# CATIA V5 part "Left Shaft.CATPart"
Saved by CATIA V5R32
Part number: Left hand shaft
Bounding box of the stored display mesh (mm): x 0 to 100, y -25 to 25, z -35 to 35
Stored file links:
  D:\PROJECTS\Project 2022\CATIA V5 6R 2022\Resources\Part Files\c16_catia_v5_6r2022_prt\CV Joint-(Fig16-51)\Left Shaft.CATPart
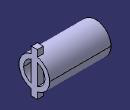
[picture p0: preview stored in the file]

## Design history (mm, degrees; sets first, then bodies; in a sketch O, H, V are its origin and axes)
Body1 (main body)
  Sketch1 on yz-plane, origin (0, 0, 0), H (0, 1, 0), V (0, 0, 1)
    circle A1 centre (0, 0) radius 25
    circle A2 centre (0, 0) radius 17.5
    radius A1 = 25
    radius A2 = 17.5
  Pad1: profile Sketch1, direction (1, 0, 0), length 100
  Sketch2 on end face of Pad1, origin (100, 0, 0), H (0, 1, 0), V (0, 0, 1)
    line L1 (5, 35) -> (5, -35)
    line L2 (5, -35) -> (-5, -35)
    line L3 (-5, -35) -> (-5, 35)
    line L4 (-5, 35) -> (5, 35)
    length L1 = 70
    length L4 = 10
    vertical: L1 V, L3 V
    horizontal: L2 H, L4 H
    equidistance: L1 L3 O, L2 L4 O
  Pad2: profile Sketch2, direction (-1, 0, 0), length 10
